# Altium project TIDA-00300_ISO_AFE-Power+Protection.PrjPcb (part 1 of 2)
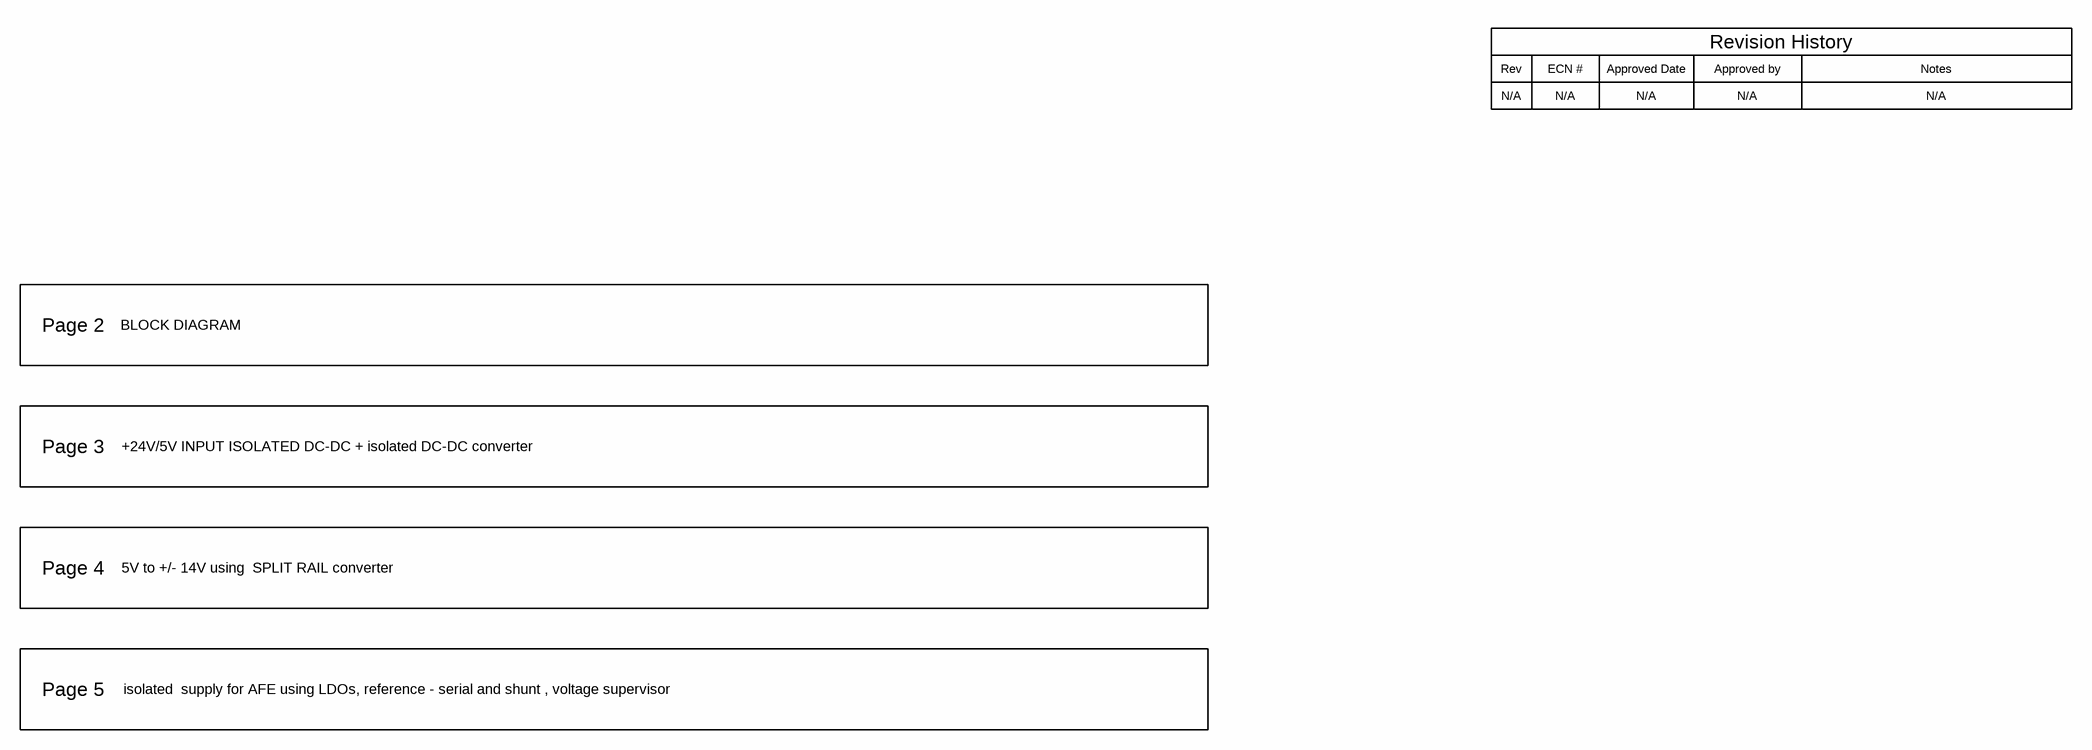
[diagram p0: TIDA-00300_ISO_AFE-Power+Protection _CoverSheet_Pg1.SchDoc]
CopyrightYear: 2019; PCB_Layout: Avinash N; PCB_Rev: E1; PRJ_Customer: Public Release; PRJ_Engineer: Sreenivasa; PRJ_Number: TIDA-00300_ISO_AFE-Power+Protection; PRJ_Title: TIDA-00300_ISO_AFE-Power+Protection; SCH_Rev: E1; TechSupport: http://www.ti.com/support; TID: 00300
6 sheets, 241 parts. Net scope: global (net labels, ports and power ports of the same name join across sheets).
Board file: TIDA-00300_ISO_AFE-Power+Protection.PcbDoc
Sheets:
  TIDA-00300_ISO_AFE-Power+Protection _CoverSheet_Pg1.SchDoc
  TIDA-00300_ISO_AFE-Power+Protection _ Block Diagram_Pg2.SchDoc
  TIDA-00300_ISO_AFE-Power+Protection _Pg3.SchDoc
  TIDA-00300_ISO_AFE-Power+Protection _Pg4.SchDoc
  TIDA-00300_ISO_AFE-Power+Protection _Pg5.SchDoc
  TIDA-00300_ISO_AFE-Power+Protection _EVM_Hardware_Pg6.SchDoc

## Sheet TIDA-00300_ISO_AFE-Power+Protection _CoverSheet_Pg1.SchDoc: Coversheet
size 431 x 279 mm; Date: Not shown in title block; ApprovedBy: Not shown in title block; CheckedBy: Not shown in title block; Author: Not shown in title block; CompanyName: Not shown in title block; DrawnBy: Sreenivasa; Engineer: Not shown in title block; Organization: Not shown in title block; Address1: Not shown in title block; Address2: Not shown in title block; Address3: Not shown in title block; Address4: Not shown in title block; DocumentNumber: 1; Revision: Use project parameter SCH_Rev; SheetNumber: 1; SheetTotal: 6; PageSetup: Record=PageOptions¦CenterHorizontal=True¦CenterVertical=True¦PrintScale=1.00¦XCorrection=1.00¦YCorrection=1.00¦PrintKind=0¦BorderSize=5000000¦LeftOffset=0¦BottomOffset=0¦Orientation=2¦PaperLength=1000¦PaperWidth=1000¦Scale=100¦PaperSource=15¦PrintQuality=600¦MediaType=1¦DitherType=10¦PaperKind=Letter¦PrintScaleMode=1

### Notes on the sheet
- Rev
- N/A
- ECN #
- Approved Date
- Approved by
- Revision History
- Notes
- Page 2
- BLOCK DIAGRAM
- Page 3
- +24V/5V INPUT ISOLATED DC-DC + isolated DC-DC converter
- Page 4
- 5V to +/- 14V using  SPLIT RAIL converter
- Page 5
- isolated  supply for AFE using LDOs, reference - serial and shunt , voltage supervisor

## Sheet TIDA-00300_ISO_AFE-Power+Protection _ Block Diagram_Pg2.SchDoc: Block Diagram
size 431 x 279 mm; Date: Not shown in title block; ApprovedBy: Not shown in title block; CheckedBy: Not shown in title block; Author: Not shown in title block; CompanyName: Not shown in title block; DrawnBy: Sreenivasa; Engineer: Sreenivasa; Organization: Not shown in title block; Address1: Not shown in title block; Address2: Not shown in title block; Address3: Not shown in title block; Address4: Not shown in title block; DocumentNumber: 1; Revision: Use project parameter SCH_Rev; SheetNumber: 2; SheetTotal: 6; PageSetup: Record=PageOptions¦CenterHorizontal=True¦CenterVertical=True¦PrintScale=1.00¦XCorrection=1.00¦YCorrection=1.00¦PrintKind=0¦BorderSize=5000000¦LeftOffset=0¦BottomOffset=0¦Orientation=2¦PaperLength=1000¦PaperWidth=1000¦Scale=100¦PaperSource=15¦PrintQuality=600¦MediaType=1¦DitherType=10¦PaperKind=Letter¦PrintScaleMode=1
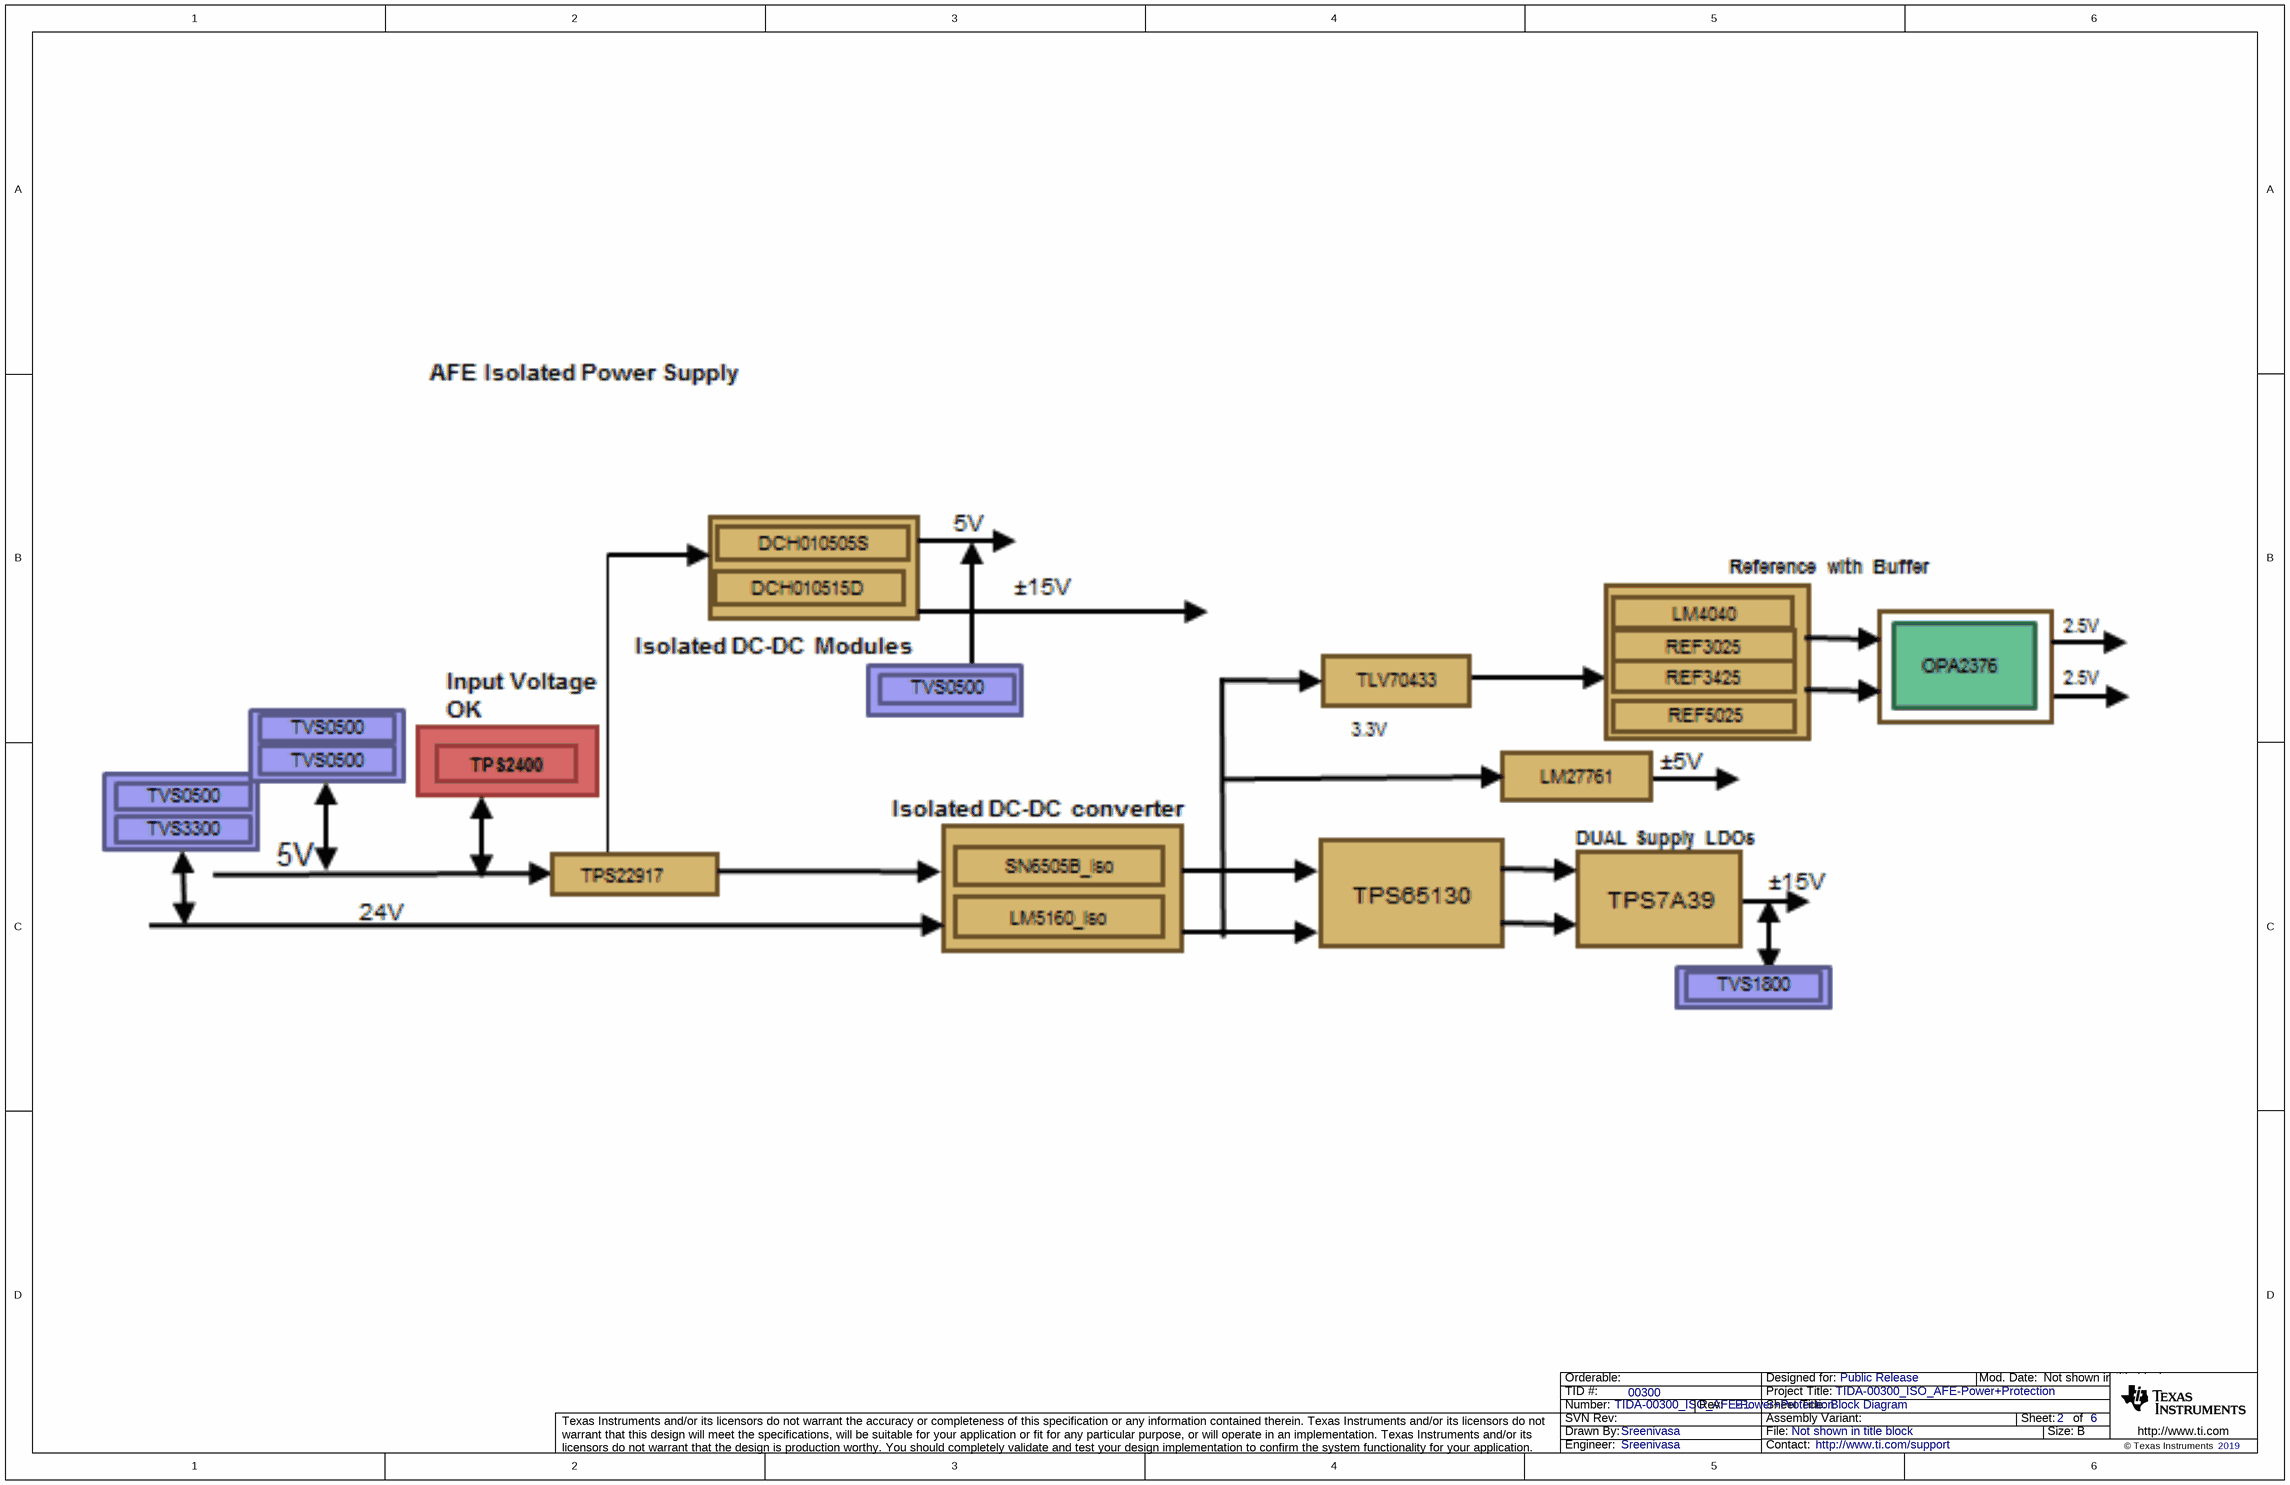
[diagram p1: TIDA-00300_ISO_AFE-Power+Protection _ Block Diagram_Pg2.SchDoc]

## Sheet TIDA-00300_ISO_AFE-Power+Protection _Pg3.SchDoc: +24V/5V INPUT ISOLATED DC-DC
size 431 x 279 mm; Date: Not shown in title block; ApprovedBy: Not shown in title block; CheckedBy: Not shown in title block; Author: Not shown in title block; CompanyName: Not shown in title block; DrawnBy: Sreenivasa; Engineer: Not shown in title block; Organization: Not shown in title block; Address1: Not shown in title block; Address2: Not shown in title block; Address3: Not shown in title block; Address4: Not shown in title block; DocumentNumber: 1; Revision: Use project parameter SCH_Rev; SheetNumber: 3; SheetTotal: 6; PageSetup: Record=PageOptions¦CenterHorizontal=True¦CenterVertical=True¦PrintScale=0.62¦XCorrection=1.00¦YCorrection=1.00¦PrintKind=0¦BorderSize=5000000¦LeftOffset=0¦BottomOffset=0¦Orientation=2¦PaperLength=1000¦PaperWidth=1000¦Scale=100¦PaperSource=15¦PrintQuality=600¦MediaType=1¦DitherType=10¦PrintScaleMode=1¦PaperKind=Letter
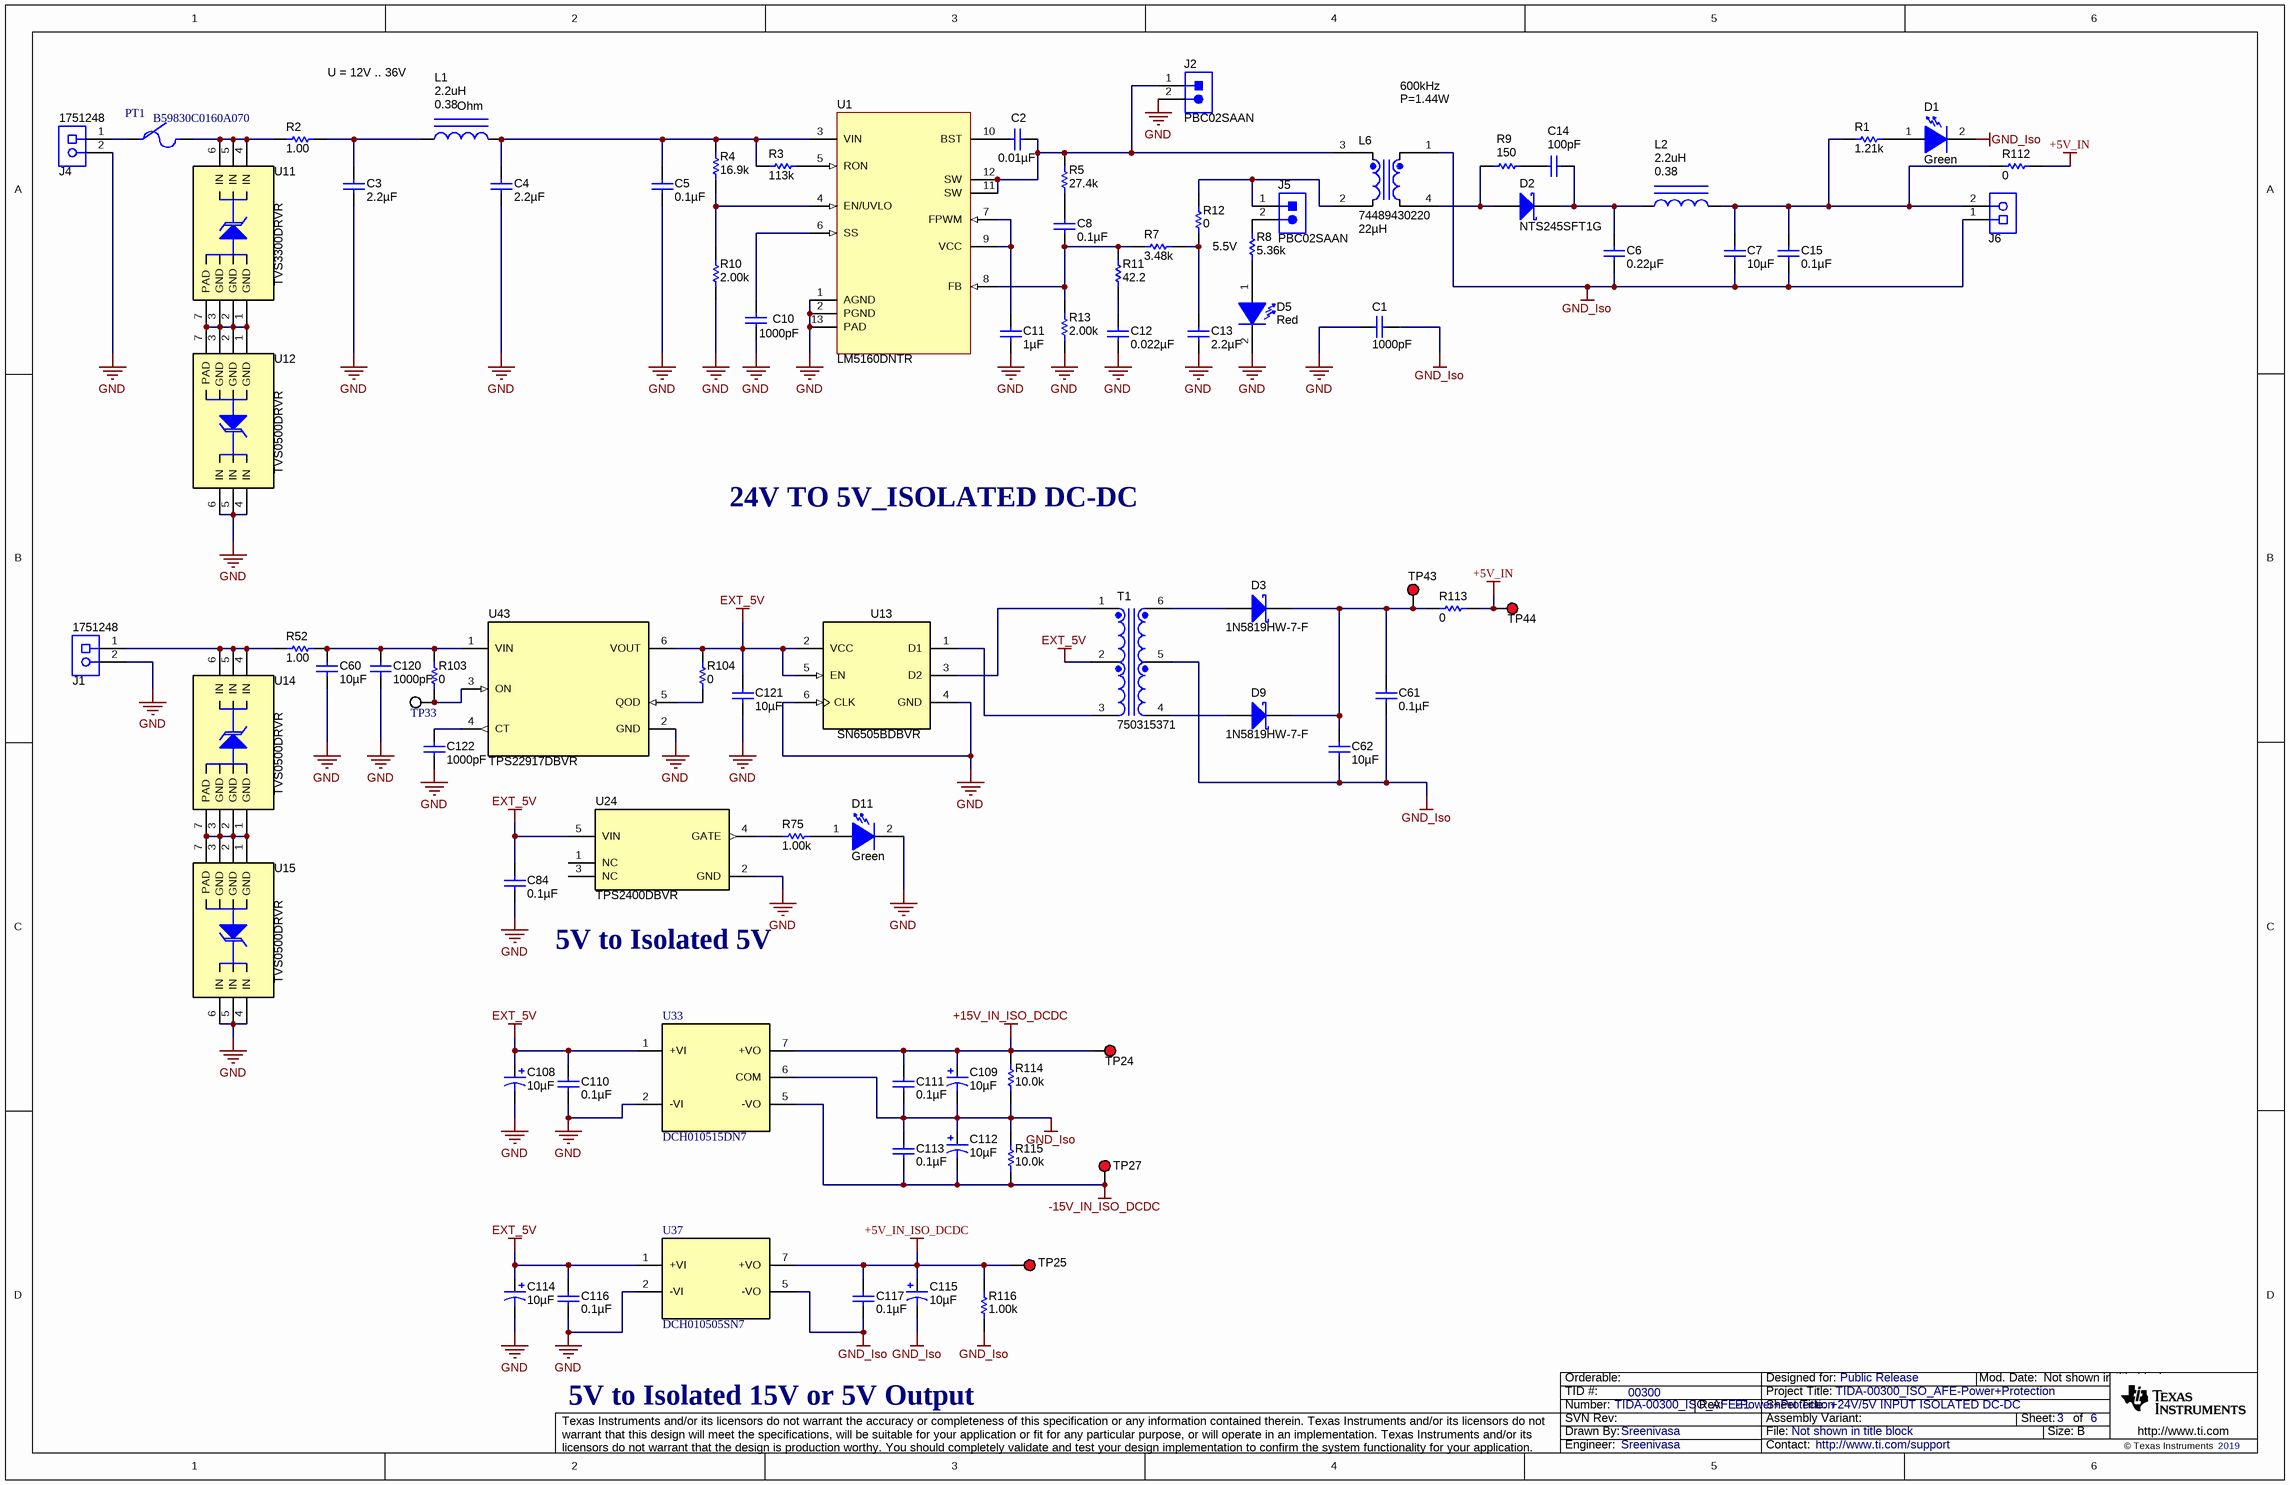
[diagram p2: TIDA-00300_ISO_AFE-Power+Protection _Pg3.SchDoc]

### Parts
C1  ValueDisplayed: 1000pF  [1206_190]  (hidden comment: 1206GC102KAZ1A)
C2  ValueDisplayed: 0.01µF  [0603S]  (hidden comment: CGA3E2X7R1H103K080AA)
C3  ValueDisplayed: 2.2µF  [1206]  (hidden comment: UMK316B7225KL-T)
C4  ValueDisplayed: 2.2µF  [1206]  (hidden comment: UMK316B7225KL-T)
C5  ValueDisplayed: 0.1µF  [0603S]  (hidden comment: C0603X124K5RAC7867)
C6  ValueDisplayed: 0.22µF  [0603]  (hidden comment: 885012206048)
C7  ValueDisplayed: 10µF  [0805_HV]  (hidden comment: GRM21BC71E106KE11L)
C8  ValueDisplayed: 0.1µF  [0603S]  (hidden comment: C0603X124K5RAC7867)
C10  ValueDisplayed: 1000pF  [0603S]  (hidden comment: 885012206034)
C11  ValueDisplayed: 1µF  [0603S]  (hidden comment: CGA3E1X7R1E105K080AC)
C12  ValueDisplayed: 0.022µF  [0603S]  (hidden comment: C1608X7R1H223K080AA)
C13  ValueDisplayed: 2.2µF  [0603]  (hidden comment: C1608X7R1A225K080AC)
C14  ValueDisplayed: 100pF  [0603S]  (hidden comment: GCM1885C1H101JA16D)
C15  ValueDisplayed: 0.1µF  [0603S]  (hidden comment: C0603X124K5RAC7867)
C60  ValueDisplayed: 10µF  [0805_HV]  (hidden comment: C2012X5R1E106K085AC)
C61  ValueDisplayed: 0.1µF  [0603]  (hidden comment: 06033D104KAT2A)
C62  ValueDisplayed: 10µF  [0805_HV]  (hidden comment: C2012X5R1E106K085AC)
C84  ValueDisplayed: 0.1µF  [0603S]  (hidden comment: C0603X124K5RAC7867)
C108  ValueDisplayed: 10µF  [6032-28]  (hidden comment: 593D106X9025C2TE3)
C109  ValueDisplayed: 10µF  [6032-28]  (hidden comment: 593D106X9025C2TE3)
C110  ValueDisplayed: 0.1µF  [0603]  (hidden comment: 06033D104KAT2A)
C111  ValueDisplayed: 0.1µF  [0603]  (hidden comment: 06033D104KAT2A)
C112  ValueDisplayed: 10µF  [6032-28]  (hidden comment: 593D106X9025C2TE3)
C113  ValueDisplayed: 0.1µF  [0603]  (hidden comment: 06033D104KAT2A)
C114  ValueDisplayed: 10µF  [6032-28]  (hidden comment: 593D106X9025C2TE3)
C115  ValueDisplayed: 10µF  [6032-28]  (hidden comment: 593D106X9025C2TE3)
C116  ValueDisplayed: 0.1µF  [0603]  (hidden comment: 06033D104KAT2A)
C117  ValueDisplayed: 0.1µF  [0603]  (hidden comment: 06033D104KAT2A)
C120  ValueDisplayed: 1000pF  [0402]  (hidden comment: CGA2B2C0G1H102J050BA)
C121  ValueDisplayed: 10µF  [0805_HV]  (hidden comment: C2012X5R1E106K085AC)
C122  ValueDisplayed: 1000pF  [0402]  (hidden comment: CGA2B2C0G1H102J050BA)
D1  value Green  [LED_LTST-C190_G]  (hidden comment: LTST-C190KGKT)
D2  NTS245SFT1G  [SOD-123FL]
D3  1N5819HW-7-F  [SOD-123]
D5  value Red  [LED_LTST-C190_Red]  (hidden comment: LTST-C190CKT)
D9  1N5819HW-7-F  [SOD-123]
D11  value Green  [LED_LTST-C190_G]  (hidden comment: LTST-C190KGKT)
J1  1751248  [CONN_1751248]
J2  PBC02SAAN  [Sullins_PBC02SAAN]
J4  1751248  [CONN_1751248]
J5  PBC02SAAN  [Sullins_PBC02SAAN]
J6  1751248  [CONN_1751248]  (value not drawn)
L1  2.2uH  DCR_ohm: 0.38  [0603L]
L2  2.2uH  DCR_ohm: 0.38  [0603]
L6  74489430220  ValueDisplayed: 22µH  [WE-TDC_8018]
PT1  B59830C0160A070  [POLYSWITCH_RXE135]
R1  ValueDisplayed: 1.21k  [0603S]  (hidden comment: CRCW06031K21FKEA)
R2  ValueDisplayed: 1.00  [0603S]  (hidden comment: CRCW06031R00FKEA)
R3  ValueDisplayed: 113k  [0603S]  (hidden comment: CRCW0603113KFKEA)
R4  ValueDisplayed: 16.9k  [0603S]  (hidden comment: CRCW060316K9FKEA)
R5  ValueDisplayed: 27.4k  [0603S]  (hidden comment: CRCW060327K4FKEA)
R7  ValueDisplayed: 3.48k  [0603S]  (hidden comment: CRCW06033K48FKEA)
R8  ValueDisplayed: 5.36k  [0603S]  (hidden comment: CRCW06035K36FKEA)
R9  ValueDisplayed: 150  [0603S]  (hidden comment: CRCW0603150RFKEA)
R10  ValueDisplayed: 2.00k  [0603S]  (hidden comment: CRCW06032K00FKEA)
R11  ValueDisplayed: 42.2  [0603S]  (hidden comment: CRCW060342R2FKEA)
R12  ValueDisplayed: 0  [0603S]  (hidden comment: ERJ-3GEY0R00V)
R13  ValueDisplayed: 2.00k  [0603S]  (hidden comment: CRCW06032K00FKEA)
R52  ValueDisplayed: 1.00  [0603S]  (hidden comment: CRCW06031R00FKEA)
R75  ValueDisplayed: 1.00k  [0603]  (hidden comment: ERJ-3EKF1001V)
R103  ValueDisplayed: 0  [0603]  (hidden comment: ERJ-3GEY0R00V)
R104  ValueDisplayed: 0  [0603]  (hidden comment: ERJ-3GEY0R00V)
R112  ValueDisplayed: 0  [0805_HV]  (hidden comment: ERJ-6GEY0R00V)
R113  ValueDisplayed: 0  [0805_HV]  (hidden comment: ERJ-6GEY0R00V)
R114  ValueDisplayed: 10.0k  [0603]  (hidden comment: RC0603FR-0710KL)
R115  ValueDisplayed: 10.0k  [0603]  (hidden comment: RC0603FR-0710KL)
R116  ValueDisplayed: 1.00k  [0603]  (hidden comment: CRCW06031K00FKEA)
T1  750315371  [Wurth_750315371]
TP24  5000  [Keystone5000]  (value not drawn)
TP25  5000  [Keystone5000]  (value not drawn)
TP27  5000  [Keystone5000]  (value not drawn)
TP33  5002  [Keystone5002]  (value not drawn)
TP43  5000  [Keystone5000]  (value not drawn)
TP44  5000  [Keystone5000]  (value not drawn)
U1  LM5160DNTR  [DNT0012B]
U11  TVS3300DRVR  [DRV0006A]
U12  TVS0500DRVR  [DRV0006A]
U13  SN6505BDBVR  [DBV0006A_N]
U14  TVS0500DRVR  [DRV0006A]
U15  TVS0500DRVR  [DRV0006A]
U24  TPS2400DBVR  [DBV0005A_N]
U33  DCH010515DN7  [EDJ0005A]
U37  DCH010505SN7  [EDJ0004A]
U43  TPS22917DBVR  [DBV0006A_N]

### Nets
+5V_IN: R112.2 R113.2 TP44.1
+5V_IN_ISO_DCDC: C115.1(+) C117.1 R116.2 TP25.1 U37.7(+VO)
+15V_IN_ISO_DCDC: C109.1(+) C111.1 R114.1 TP24.1 U33.7(+VO)
-15V_IN_ISO_DCDC: C112.2(-) C113.2 R115.2 TP27.1 U33.5(-VO)
EXT_5V: C84.1 C108.1(+) C110.1 C114.1(+) C116.1 C121.1 R104.2 T1.2 U13.2(VCC) U13.5(EN) U24.5(VIN) U33.1(+VI) U37.1(+VI) U43.6(VOUT)
GND: C1.2 C3.2 C4.2 C5.2 C10.2 C11.2 C12.2 C13.2 C60.2 C84.2 C108.2(-) C110.2 C114.2(-) C116.2 C120.2 C121.2 C122.2 D5.2(K) D11.2(K) J1.2 J2.2 J4.2 R10.1 R13.1 U1.1(AGND) U1.2(PGND) U1.13(PAD) U12.4(IN) U12.5(IN) U12.6(IN) U13.4(GND) U13.6(CLK) U15.4(IN) U15.5(IN) U15.6(IN) U24.2(GND) U33.2(-VI) U37.2(-VI) U43.2(GND)
GND_Iso: C1.1 C6.2 C7.2 C15.2 C61.2 C62.1 C109.2(-) C111.2 C112.1(+) C113.1 C115.2(-) C117.2 D1.2(K) J6.1 L6.1 R114.2 R115.1 R116.1 T1.5 U33.6(COM) U37.5(-VO)
NetC2_1: C2.1 U1.10(BST)
NetC2_2: C2.2 J2.1 L6.3 R5.1 U1.11(SW) U1.12(SW)
NetC3_1: C3.1 L1.1 R2.1
NetC4_1: C4.1 C5.1 L1.2 R3.1 R4.2 U1.3(VIN)
NetC6_1: C6.1 C14.2 D2.1(K) L2.1
NetC7_1: C7.1 C15.1 J6.2 L2.2 R1.1 R112.1
NetC8_1: C8.1 R5.2
NetC8_2: C8.2 R7.1 R11.2 R13.2 U1.8(FB)
NetC10_1: C10.1 U1.6(SS)
NetC11_1: C11.1 U1.7(FPWM) U1.9(VCC)
NetC12_1: C12.1 R11.1
NetC13_1: C13.1 R7.2 R12.1
NetC14_1: C14.1 R9.1
NetC60_1: C60.1 C120.1 R52.1 R103.2 U43.1(VIN)
NetC61_1: C61.1 C62.2 D3.1(K) D9.1(K) R113.1 TP43.1
NetC122_1: C122.1 U43.4(CT)
NetD1_1: D1.1(A) R1.2
NetD2_2: D2.2(A) L6.4 R9.2
NetD3_2: D3.2(A) T1.6
NetD5_1: D5.1(A) R8.1
NetD9_2: D9.2(A) T1.4
NetD11_1: D11.1(A) R75.2
NetJ1_1: J1.1 R52.2 U14.4(IN) U14.5(IN) U14.6(IN)
NetJ4_1: J4.1 PT1.1
NetJ5_1: J5.1 L6.2 R12.2
NetJ5_2: J5.2 R8.2
NetPT1_2: PT1.2 R2.2 U11.4(IN) U11.5(IN) U11.6(IN)
NetR3_2: R3.2 U1.5(RON)
NetR4_1: R4.1 R10.2 U1.4(EN/UVLO)
NetR75_1: R75.1 U24.4(GATE)
NetR103_1: R103.1 TP33.1 U43.3(ON)
NetR104_1: R104.1 U43.5(QOD)
NetT1_1: T1.1 U13.3(D2)
NetT1_3: T1.3 U13.1(D1)
NetU11_1: U11.1(GND) U11.2(GND) U11.3(GND) U11.7(PAD) U12.1(GND) U12.2(GND) U12.3(GND) U12.7(PAD)
NetU14_1: U14.1(GND) U14.2(GND) U14.3(GND) U14.7(PAD) U15.1(GND) U15.2(GND) U15.3(GND) U15.7(PAD)

Not connected (* = marked no-connect by the designer): U24 1(NC) 3(NC)

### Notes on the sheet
- U = 12V .. 36V
- (near L6) P=1.44W
- 600kHz
- (near L1) Ohm
- 5.5V
- 24V TO 5V_ISOLATED DC-DC
- 5V to Isolated 5V
- 5V to Isolated 15V or 5V Output

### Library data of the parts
C1 = 202R18W102KV4E: CAP, CERM, 1000 pF, 2000 V, +/- 10%, X7R, 1206_190; Manufacturer: AVX; Polarized: N; CompType: Capacitor; Value: 1000pF; U/M: EA; Cap_F: 0.000000001; Tolerance_%: 10; Value1: Unknown; VDC_V: 2000; Value2: 2000V; TaMin_C: -55; TaMax_C: 125; Cap_Case: 1206
C2 = C0603C103J5RACTU: CAP, CERM, 0.01 µF, 50 V, +/- 5%, X7R, 0603; Manufacturer: TDK Corporation; Polarized: N; CompType: Capacitor; Value: 0.01uF; U/M: EA; Cap_F: 0.00000001; Tolerance_%: 5; Value1: Unknown; VDC_V: 50; Value2: 50V; TaMin_C: -55; TaMax_C: 125; Cap_Case: 0603; AEC Category: Q200
C3 C4 = UMK316B7225KL-T: CAP, CERM, 2.2 µF, 50 V,+/- 10%, X7R, 1206; Manufacturer: Taiyo Yuden; Polarized: N; CompType: Capacitor; Value: 2.2uF; U/M: EA; Cap_F: 0.0000022; Tolerance_%: 10; VDC_V: 50; Value2: 50V; TaMin_C: -55; TaMax_C: 125; AEC Category: Q200; SizeArea_mm2: 5.12; SizeAreaWB_mm2: 10.92; SizeX_mm: 3.2; SizeY_mm: 1.6; SizeZ_mm: 1.35
C5 C8 C15 C84 = C1608X7R1H104K: CAP, CERM, 0.12µF ±10% 50V Ceramic Capacitor X7R 0603; Manufacturer: KEMET; Polarized: N; Value: 0.1uF; U/M: EA; Cap_F: 0.0000001; Tolerance_%: 10; ESR_ohm: 0.017; Value1: 0.017 ohm; VDC_V: 50; TaMin_C: -55; TaMax_C: 125; Cap_Case: 0603; AEC Category: Q200
C6 = 885012206048: CAP, CERM, 0.22 µF, 16 V, +/- 10%, X7R, 0603; Manufacturer: Wurth Elektronik; Polarized: N; CompType: Capacitor; Value: 0.22uF; U/M: EA; Cap_F: 0.00000022; Tolerance_%: 10; Value1: Unknown; VDC_V: 16; Value2: 16V; TaMin_C: -55; TaMax_C: 125; AEC Category: Q200
C7 = GRM21BC71E106KE11L: CAP, CERM, 10 µF, 25 V,+/- 10%, X7S, 0805; Manufacturer: MuRata; Polarized: N; CompType: Capacitor; Value: 10uF; U/M: EA; Cap_F: 0.00001; Tolerance_%: 10; VDC_V: 25; Value2: 25V; TaMin_C: -55; TaMax_C: 125; Cap_Case: 0805; AEC Category: Q200; SizeArea_mm2: 2.5; SizeAreaWB_mm2: 6.75; SizeX_mm: 2; SizeY_mm: 1.25; SizeZ_mm: 1.45
C10 = 885012206034: CAP, CERM, 1000 pF, 16 V, +/- 10%, X7R, 0603; Manufacturer: Wurth Elektronik; Polarized: N; CompType: Capacitor; Value: 1000pF; U/M: EA; Cap_F: 0.000000001; Tolerance_%: 10; Value1: Unknown; VDC_V: 16; Value2: 16V; TaMin_C: -55; TaMax_C: 125; Cap_Case: 0603; AEC Category: Q200
C11 = GRM188R71E105KA12D: CAP, CERM, 1 µF, 25 V, +/- 10%, X7R, 0603; Manufacturer: TDK Corporation; Polarized: N; CompType: Capacitor; Value: 1uF; U/M: EA; Cap_F: 0.000001; Tolerance_%: 10; Value1: Unknown; VDC_V: 25; Value2: 25V; TaMin_C: -55; TaMax_C: 125; Cap_Case: 0603; AEC Category: Q200
C12 = GRM188R71H223KA01D: CAP, CERM, 0.022 µF, 50 V, +/- 10%, X7R, 0603; Manufacturer: TDK Corporation; Polarized: N; CompType: Capacitor; Value: 0.022uF; U/M: EA; Cap_F: 0.000000022; Tolerance_%: 10; Value1: Unknown; VDC_V: 50; Value2: 50V; TaMin_C: -55; TaMax_C: 125; Cap_Case: 0603; AEC Category: Q200
C13 = C1608X7R1A225K080AC: CAP, CERM, 2.2 µF, 10 V,+/- 10%, X7R, 0603; Manufacturer: TDK; Polarized: N; CompType: Capacitor; Value: 2.2uF; U/M: EA; Cap_F: 0.0000022; Tolerance_%: 10; ESR_ohm: 0.004058; Value1: 0.004058 ohm; Value2: 10V; IRMS_A: 2.58266; TaMin_C: -55; TaMax_C: 125; AEC Category: Q200; SizeArea_mm2: 1.28; SizeAreaWB_mm2: 4.68; SizeX_mm: 1.6; SizeY_mm: 0.8; SizeZ_mm: 1; Green_Lifecycle: Active; Green_REACh: Passed
C14 = C0603C101J5GACTU: CAP, CERM, 100 pF, 50 V, +/- 5%, C0G/NP0, 0603; Manufacturer: Murata; Polarized: N; CompType: Capacitor; Value: 100pF; U/M: EA; Cap_F: 0.0000000001; Tolerance_%: 5; Value1: Unknown; VDC_V: 50; Value2: 50V; TaMin_C: -55; TaMax_C: 125; Cap_Case: 0603; AEC Category: Q200
C60 C62 C121 = GRM21BR61E106KA73L: CAP, CERM, 10 µF, 25 V, +/- 10%, X5R, 0805; Manufacturer: TDK Corporation; Polarized: N; CompType: Capacitor; Value: 10uF; U/M: EA; Cap_F: 0.00001; Tolerance_%: 10; Value1: Unknown; VDC_V: 25; Value2: 25V; TaMin_C: -55; TaMax_C: 85; Cap_Case: 0805; AEC Category: Q200
C61 = 06033D104KAT2A: CAP, CERM, 0.1 µF, 25 V,+/- 10%, X5R, 0603; Manufacturer: AVX; Polarized: N; CompType: Capacitor; Value: 0.1uF; U/M: EA; Cap_F: 0.0000001; Tolerance_%: 10; ESR_ohm: 0.048; Value1: 0.048 ohm; VDC_V: 25; Value2: 25V; IRMS_A: 0.53; TaMin_C: -55; TaMax_C: 85; AEC Category: Q200; SizeArea_mm2: 1.28; SizeAreaWB_mm2: 4.68; SizeX_mm: 1.6; SizeY_mm: 0.8; SizeZ_mm: 1; Green_Lifecycle: Active; Green_REACh: Passed
C108 C109 C112 C114 C115 = 593D106X9025C2TE3: CAP, TA, 10 µF, 25 V, +/- 10%, 0.45 ohm, SMD; Manufacturer: Vishay-Sprague; Polarized: Y; CompType: Capacitor; Value: 10uF; U/M: EA; Cap_F: 0.00001; Tolerance_%: 10; VDC_V: 25; Value2: 25V; ESR_ohm: 0.45; IRMS_A: 0.49; TaMin_C: -55; TaMax_C: 125; Cap_Case: C; SizeAreaWB_mm2: 41.6; SizeArea_mm2: 19.2; SizeX_mm: 6; SizeY_mm: 3.2; SizeZ_mm: 2.8; AEC Category: Q200
C110 C111 C113 C116 C117 = 06033D104KAT2A: CAP, CERM, 0.1 µF, 25 V,+/- 10%, X5R, 0603; Manufacturer: AVX; Polarized: N; CompType: Capacitor; Value: 0.1uF; U/M: EA; Cap_F: 0.0000001; Tolerance_%: 10; ESR_ohm: 0.048; Value1: 0.048 ohm; VDC_V: 25; Value2: 25V; IRMS_A: 0.53; TaMin_C: -55; TaMax_C: 85; SizeArea_mm2: 1.28; SizeAreaWB_mm2: 4.68; SizeX_mm: 1.6; SizeY_mm: 0.8; SizeZ_mm: 1; AEC Category: Q200; Green_Lifecycle: Active; Green_REACh: Passed
C120 C122 = CGA2B2C0G1H102J050BA: CAP, CERM, 1000 pF, 50 V,+/- 5%, C0G/NP0, AEC-Q200 Grade 1, 0402; Manufacturer: TDK; Polarized: N; CompType: Capacitor; Value: 1000pF; U/M: EA; Cap_F: 0.000000001; Tolerance_%: 5; VDC_V: 50; Value2: 50V; TaMin_C: -55; TaMax_C: 125; SizeArea_mm2: 0.5; SizeAreaWB_mm2: 3; SizeX_mm: 1; SizeZ_mm: 0.6; AEC Category: Q200; AEC Qualified: Y; Green_Lifecycle: Active; Green_REACh: Passed
D1 D11 = LTST-C190KGKT: LED, Green, SMD; Manufacturer: Lite-On; Type: AlInGaP; Vf_V: 2; Value2: 2V; Io_A: 0.03; Tjmax_C: 85; Value1: W; U/M: EA
D2 = NTS245SFT1G: Diode, Schottky, 45 V, 2 A, AEC-Q101, SOD-123FL; Manufacturer: ON Semiconductor; U/M: EA; Vf_V: 0.63; Value: 45V; Value1: 2A; Value2: 0.63V; Io_A: 2; Vr_V: 45; TJmax_C: 150; AEC Category: Q101; AEC Qualified: Y
D3 D9 = 1N5819HW-7-F: Diode, Schottky, 40 V, 1 A, SOD-123; Manufacturer: Diodes Inc.; U/M: EA; Vf_V: 0.45; Value: 40V; Value1: 1A; Value2: 0.45V; Io_A: 1; Vr_V: 40; TJmax_C: 125; SizeAreaWB_mm2: 13.095; SizeArea_mm2: 6.545; SizeX_mm: 3.85; SizeY_mm: 1.7; SizeZ_mm: 1.35; AEC Category: Q101
D5 = LTST-C190CKT: LED, Red, SMD; Manufacturer: Lite-On; Vf_V: 2; Value2: 2V; Io_A: 0.02; Tjmax_C: 85; Power_TotalModule: 0.0625; Value1: 0.0625W; U/M: EA
J1 J4 J6 = 1751248: Conn Term Block, 2POS, 3.5mm, TH; Manufacturer: Phoenix Contact; CompType: Terminal Block; SymbolCreator: a0412235
J2 J5 = PBC02SAAN: Header, 100mil, 2x1, Gold, TH; Manufacturer: Sullins Connector Solutions; SymbolCreator: a0412235; Pitch_mm: 2.54; Gender: Male; Shrouded: N; Row_Count: 1; Current_A: 3; Voltage_V: 1800; Cert_UL: Y; Green_Lifecycle: Active; Green_REACh: Passed
L1 L2 = LQM18PN2R2MFH: Inductor, Ferrite, 2.2 µH, 0.35 A, 0.38 ohm, SMD; Manufacturer: MuRata; Imax_A: 0.35; Value2: 0.35A; Ind_H: 2.2E-6; ValueDisplayed: 2.2µH; Irms: 0.9A @ 40C rise; Isat: 0.35A @ 30% inductance drop; AEC Category: Q200
L6 = 74489430220: Coupled inductor, 22 µH, 1.1 A, 0.48 ohm, SMD; Manufacturer: Wurth Elektronik; SymbolCreator: Altium; Value: 22uH; Ind_H: 22.0E-6; DCR_ohm: 0.48
PT1 = POLYSWITCH_RXE135: PTC THERMISTOR C 830-A 160-A 70; Manufacturer: Raychem; Manufacturer: EPCOS (TDK); Area: 93750
R1 = CRCW06031K21FKEA: RES, 1.21 k, 1%, 0.1 W, 0603; Manufacturer: Vishay-Dale; CompType: Resistor; Value: 1.21k; Res_ohm: 1210; Value_Code: 1k21; Tolerance_%: 1; Power_W: 0.1; Value2: 0.1W; VDC_V: 75; TempCo: 100 ppm/C; EIA_Code: E96; U/M: EA; AEC Category: Q200
R2 R52 = CRCW06031R00FKEA: RES, 1.00, 1%, 0.1 W, 0603; Manufacturer: Vishay-Dale; CompType: Resistor; Value: 1.00; Res_ohm: 1; Value_Code: 1R00; Power_W: 0.1; Value2: 0.1W; VDC_V: 75; TempCo: 100 ppm/C; EIA_Code: E96; U/M: EA; AEC Category: Q200
R3 = CRCW0603113KFKEA: RES, 113 k, 1%, 0.1 W, 0603; Manufacturer: Vishay-Dale; CompType: Resistor; Value: 113k; Res_ohm: 113000; Tolerance_%: 1; Power_W: 0.1; Value2: 0.1W; VDC_V: 75; TempCo: 100 ppm/C; EIA_Code: E96; U/M: EA; AEC Category: Q200
R4 = CRCW060316K9FKEA: RES, 16.9 k, 1%, 0.1 W, 0603; Manufacturer: Vishay-Dale; CompType: Resistor; Value: 16.9k; Res_ohm: 16900; Value_Code: 16k9; Tolerance_%: 1; Power_W: 0.1; Value2: 0.1W; VDC_V: 75; TempCo: 100 ppm/C; EIA_Code: E96; U/M: EA; AEC Category: Q200
R5 = CRCW060327K4FKEA: RES, 27.4 k, 1%, 0.1 W, 0603; Manufacturer: Vishay-Dale; CompType: Resistor; Value: 27.4k; Res_ohm: 27400; Value_Code: 27k4; Tolerance_%: 1; Power_W: 0.1; Value2: 0.1W; VDC_V: 75; TempCo: 100 ppm/C; EIA_Code: E96; U/M: EA; AEC Category: Q200
R7 = CRCW06033K48FKEA: RES, 3.48 k, 1%, 0.1 W, 0603; Manufacturer: Vishay-Dale; CompType: Resistor; Value: 3.48k; Res_ohm: 3480; Value_Code: 3k48; Tolerance_%: 1; Power_W: 0.1; Value2: 0.1W; VDC_V: 75; TempCo: 100 ppm/C; EIA_Code: E96; U/M: EA; AEC Category: Q200
R8 = CRCW06035K36FKEA: RES, 5.36 k, 1%, 0.1 W, 0603; Manufacturer: Vishay-Dale; CompType: Resistor; Value: 5.36k; Res_ohm: 5360; Value_Code: 5k36; Tolerance_%: 1; Power_W: 0.1; Value2: 0.1W; VDC_V: 75; TempCo: 100 ppm/C; EIA_Code: E96; U/M: EA; AEC Category: Q200
R9 = CRCW0603150RFKEA: RES, 150, 1%, 0.1 W, 0603; Manufacturer: Vishay-Dale; CompType: Resistor; Value: 150; Value_Code: 150R; Tolerance_%: 1; Power_W: 0.1; Value2: 0.1W; VDC_V: 75; TempCo: 100 ppm/C; EIA_Code: E96; U/M: EA; AEC Category: Q200
R10 R13 = CRCW06032K00FKEA: RES, 2.00 k, 1%, 0.1 W, 0603; Manufacturer: Vishay-Dale; CompType: Resistor; Value: 2.00k; Res_ohm: 2000; Value_Code: 2k00; Tolerance_%: 1; Power_W: 0.1; Value2: 0.1W; VDC_V: 75; TempCo: 100 ppm/C; EIA_Code: E96; U/M: EA; AEC Category: Q200
R11 = CRCW060342R2FKEA: RES, 42.2, 1%, 0.1 W, 0603; Manufacturer: Vishay-Dale; CompType: Resistor; Value: 42.2; Value_Code: 42R2; Tolerance_%: 1; Power_W: 0.1; Value2: 0.1W; VDC_V: 75; TempCo: 100 ppm/C; EIA_Code: E96; U/M: EA; AEC Category: Q200
R12 = ERJ-3GEY0R00V: RES, 0, 5%, 0.1 W, 0603; Manufacturer: Panasonic; CompType: Resistor; Value: 0; Value_Code: 0000; Tolerance_%: 5; Power_W: 0.1; Value2: 0.1W; VDC_V: 50; TempCo: 600 ppm/C; EIA_Code: E24; U/M: EA; AEC Category: Q200
R75 = ERJ-3EKF1001V: RES, 1.00 k, 1%, 0.1 W, AEC-Q200 Grade 0, 0603; Manufacturer: Panasonic; CompType: Resistor; Value: 1.00k; Res_ohm: 1000; Value_Code: 1k00; Tolerance_%: 1; Power_W: 0.1; Value2: 0.1W; VDC_V: 75; TempCo: 100 ppm/C; SizeArea_mm2: 1.28; SizeX_mm: 1.6; SizeY_mm: 0.8; EIA_Code: E96; U/M: EA; AEC Category: Q200; AEC Qualified: Y; AEC Grade: 0; Green_Lifecycle: Active; Green_REACh: Passed
R103 R104 = ERJ-3GEY0R00V: RES, 0, 5%, 0.1 W, 0603; Manufacturer: Panasonic; CompType: Resistor; Value: 0; Value_Code: 0000; Tolerance_%: 5; Power_W: 0.1; Value2: 0.1W; VDC_V: 50; TempCo: 600 ppm/C; SizeArea_mm2: 1.28; SizeX_mm: 1.6; SizeY_mm: 0.8; SizeZ_mm: 1; EIA_Code: E24; U/M: EA; AEC Category: Q200; Green_Lifecycle: Active; Green_REACh: Passed
R112 R113 = ERJ-6GEY0R00V: RES, 0, 5%, 0.125 W, 0805; Manufacturer: Panasonic; CompType: Resistor; Value: 0; Value_Code: 0000; Tolerance_%: 5; Power_W: 0.125; Value2: 0.125W; VDC_V: 150; TempCo: 600 ppm/C; SizeArea_mm2: 2.5; SizeX_mm: 2; SizeY_mm: 1.25; SizeZ_mm: 1.45; EIA_Code: E24; U/M: EA; AEC Category: Q200; Green_Lifecycle: Active; Green_REACh: Passed
R114 R115 = RC0603FR-0710KL: RES, 10.0 k, 1%, 0.1 W, 0603; Manufacturer: Yageo America; CompType: Resistor; Value: 10.0k; Res_ohm: 10000; Value_Code: 10k0; Tolerance_%: 1; Power_W: 0.1; Value2: 0.1W; VDC_V: 150; TempCo: 200 ppm/C; SizeArea_mm2: 1.28; SizeX_mm: 1.6; SizeY_mm: 0.8; EIA_Code: E96; U/M: EA; AEC Category: Q200; Green_Lifecycle: Active; Green_REACh: Passed
R116 = CRCW06031K00FKEA: RES, 1.00 k, 1%, 0.1 W, 0603; Manufacturer: Vishay-Dale; CompType: Resistor; Value: 1.00k; Res_ohm: 1000; Value_Code: 1k00; Tolerance_%: 1; Power_W: 0.1; Value2: 0.1W; VDC_V: 75; TempCo: 100 ppm/C; SizeArea_mm2: 1.28; SizeX_mm: 1.6; SizeY_mm: 0.8; EIA_Code: E96; U/M: EA; AEC Category: Q200; Green_Lifecycle: Active; Green_REACh: Passed
T1 = CMP-0030623-1: Transformer, 105uH, TH; Manufacturer: Wurth Elektronik; Green_Lifecycle: Active; DCR_ohm: 0.06; Green_REACh: Passed; Lp: 105; Ns1toNp: 1.1; Ind_H: 105µH
TP24 TP25 TP27 TP43 TP44 = 5000: Test Point, Miniature, Red, TH; Manufacturer: Keystone; CompType: Test Point Loop; ContactFinish: Silver
TP33 = 5002: Test Point, Miniature, White, TH; Manufacturer: Keystone; CompType: Test Point Loop; ContactFinish: Silver; Green_Lifecycle: Active; Green_REACh: Passed
U1 = LM5160DNTR: Wide Input 65V, 1.5A Synchronous Step-Down DC-DC Converter, DNT0012B; Alternate PartNumber: LM5160DNTT; Manufacturer: Texas Instruments; SymbolCreator: a0411947; CompType: IC; U/M: EA
U11 = CMP-0013424-7: 33-V Precision Surge Protection Clamp, DRV0006A (WSON-6); Manufacturer: Texas Instruments; Alternate PartNumber: TVS3300DRVT; SizeX_mm: 2; CompType: IC; SizeZ_mm: 0.8; SizeArea_mm2: 4; SizeAreaWB_mm2: 9; U/M: EA
U12 U14 U15 = CMP-0077837-1: 5-V Precision Surge Protection Clamp, DRV0006A (WSON-6); Alternate Manufacturer: Texas Instruments; SizeAreaWB_mm2: 9.0; SizeZ_mm: 0.8; SizeX_mm: 2.0; SizeArea_mm2: 4.0; CompType: IC; AEC Qualified: N; AEC Category: Q200
U13 = SN6505BDBVR: LOW-NOISE 1A TRANSFORMER DRIVERS FOR ISOLATED POWER SUPPLIES, DBV0006A; Alternate PartNumber: SN6505BDBVT; Manufacturer: Texas Instruments; SymbolCreator: Altium; SizeArea_mm2: 8.12; SizeAreaWB_mm2: 14.82; SizeX_mm: 2.8; SizeY_mm: 2.9; SizeZ_mm: 1.45; CompType: IC; U/M: EA
U24 = CMP-0067322-1: Overvoltage/Undervoltage Protection IC in SOT-23-5, DBV0005A (SOT-23-5); Alternate PartNumber: TPS2400DBVT; Alternate Manufacturer: Texas Instruments; Green_Lifecycle: Active; SizeAreaWB_mm2: 14.82; Green_REACh: Passed; U/M: EA; SizeZ_mm: 1.45; SizeX_mm: 2.8; SizeY_mm: 2.9; SizeArea_mm2: 8.12
U33 = CMP-0030760-1: Miniature, 1 W, 3 kVDC Isolated DC-DC Converter, -40 to 85 degC, 5-pin Module (EDJ5), Pb-Free (RoHS); Manufacturer: Texas Instruments; Vout(Min)(V): 14.25; Vin(Max)(V): 5.5; Iout(Max)(A): 0.033; Regulated Outputs(#): 2; Vin(Min)(V): 4.5; SubFamily: 1 W & 2 W Miniature; Vout(Max)(V): 15.75
U37 = CMP-0030757-1: Miniature, 1 W, 3 kVDC Isolated DC-DC Converter, -40 to 85 degC, 4-pin Module (EDJ4), Pb-Free (RoHS); Manufacturer: Texas Instruments; Regulated Outputs(#): 1; Vin(Max)(V): 5.5; Vin(Min)(V): 4.5; SubFamily: 1 W & 2 W Miniature; Iout(Max)(A): 0.2
U43 = CMP-0077265-1: 5.5-V, 2-A, 80 mohm Low Leakage Load Switch with RCB and Programmable Rise Time, DBV0006A (SOT-23-6); Alternate PartNumber: TPS22917DBVT; Alternate Manufacturer: Texas Instruments; SizeAreaWB_mm2: 14.82; SizeZ_mm: 1.45; SizeX_mm: 2.8; SizeY_mm: 2.9; SizeArea_mm2: 8.12; CompType: IC; AEC Qualified: N; AEC Category: Q200

## Sheet TIDA-00300_ISO_AFE-Power+Protection _Pg4.SchDoc: +/- 14V SPLIT RAIL
size 431 x 279 mm; Date: Not shown in title block; ApprovedBy: Not shown in title block; CheckedBy: Not shown in title block; Author: Not shown in title block; CompanyName: Not shown in title block; DrawnBy: Sreenivasa; Engineer: Not shown in title block; Organization: Not shown in title block; Address1: Not shown in title block; Address2: Not shown in title block; Address3: Not shown in title block; Address4: Not shown in title block; DocumentNumber: 1; Revision: Use project parameter SCH_Rev; SheetNumber: 4; SheetTotal: 6; PageSetup: Record=PageOptions¦CenterHorizontal=True¦CenterVertical=True¦PrintScale=0.62¦XCorrection=1.00¦YCorrection=1.00¦PrintKind=0¦BorderSize=5000000¦LeftOffset=0¦BottomOffset=0¦Orientation=2¦PaperLength=1000¦PaperWidth=1000¦Scale=100¦PaperSource=15¦PrintQuality=600¦MediaType=1¦DitherType=10¦PrintScaleMode=1¦PaperKind=Letter
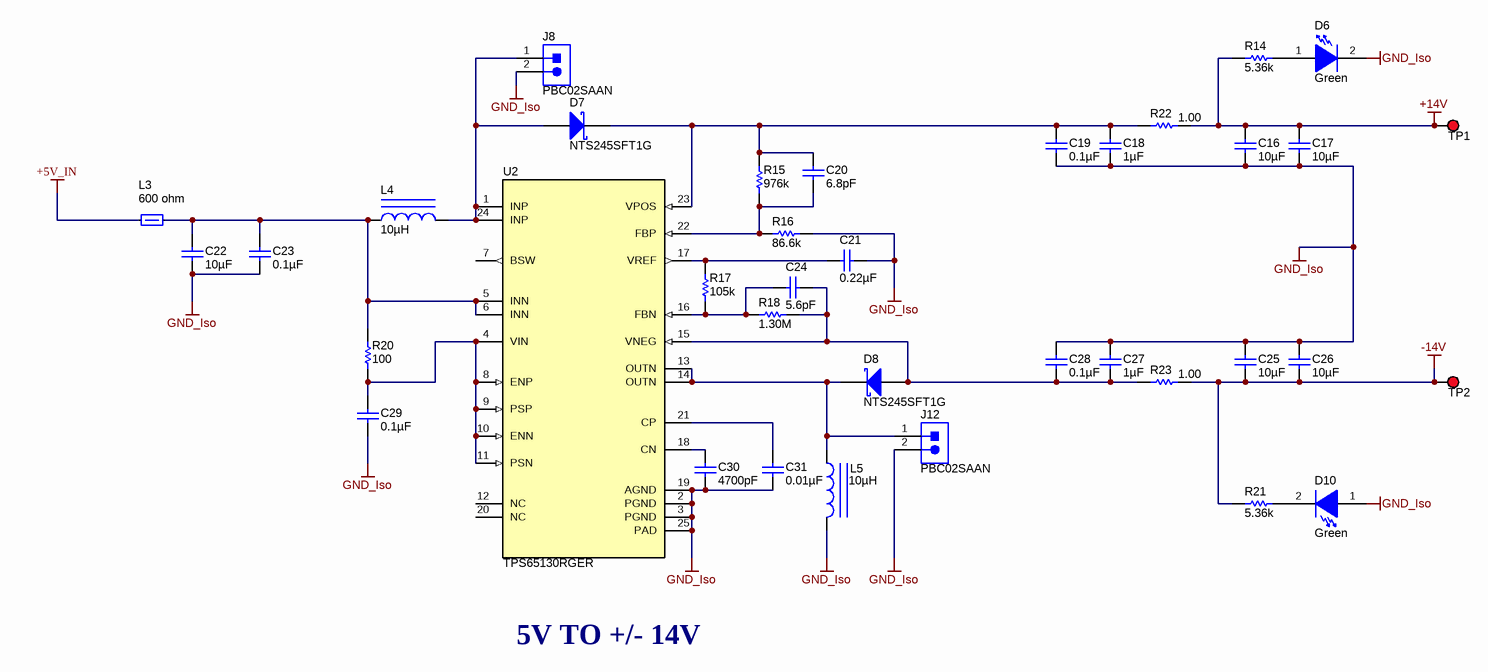
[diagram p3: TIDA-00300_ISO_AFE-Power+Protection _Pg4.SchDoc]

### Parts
C16  ValueDisplayed: 10µF  [0805_HV]  (hidden comment: GRM21BC71E106KE11L)
C17  ValueDisplayed: 10µF  [0805_HV]  (hidden comment: GRM21BC71E106KE11L)
C18  ValueDisplayed: 1µF  [0603S]  (hidden comment: CGA3E1X7R1E105K080AC)
C19  ValueDisplayed: 0.1µF  [0603S]  (hidden comment: C0603X124K5RAC7867)
C20  ValueDisplayed: 6.8pF  [0603S]  (hidden comment: 06035A6R8CAT2A)
C21  ValueDisplayed: 0.22µF  [0603S]  (hidden comment: GRM188R71C224KA01D)
C22  ValueDisplayed: 10µF  [0805_HV]  (hidden comment: GRM21BC71E106KE11L)
C23  ValueDisplayed: 0.1µF  [0603S]  (hidden comment: C0603X124K5RAC7867)
C24  ValueDisplayed: 5.6pF  [0603S]  (hidden comment: GRM1885C1H5R6DA01D)
C25  ValueDisplayed: 10µF  [0805_HV]  (hidden comment: GRM21BC71E106KE11L)
C26  ValueDisplayed: 10µF  [0805_HV]  (hidden comment: GRM21BC71E106KE11L)
C27  ValueDisplayed: 1µF  [0603S]  (hidden comment: CGA3E1X7R1E105K080AC)
C28  ValueDisplayed: 0.1µF  [0603S]  (hidden comment: C0603X124K5RAC7867)
C29  ValueDisplayed: 0.1µF  [0603S]  (hidden comment: C0603X124K5RAC7867)
C30  ValueDisplayed: 4700pF  [0603S]  (hidden comment: 885012206087)
C31  ValueDisplayed: 0.01µF  [0603S]  (hidden comment: 885012206040)
D6  value Green  [LED_LTST-C190_G]  (hidden comment: LTST-C190KGKT)
D7  NTS245SFT1G  [SOD-123FL]
D8  NTS245SFT1G  [SOD-123FL]
D10  value Green  [LED_LTST-C190_G]  (hidden comment: LTST-C190KGKT)
J8  PBC02SAAN  [Sullins_PBC02SAAN]
J12  PBC02SAAN  [Sullins_PBC02SAAN]
L3  value 600 ohm  [0603]  (hidden comment: BLM18KG601SN1D)
L4  ValueDisplayed: 10µH  [WE_LQS_252012]  (hidden comment: 74404024100)
L5  ValueDisplayed: 10µH  [WE_LQS_252012]  (hidden comment: 74404024100)
R14  ValueDisplayed: 5.36k  [0603S]  (hidden comment: CRCW06035K36FKEA)
R15  ValueDisplayed: 976k  [0603S]  (hidden comment: CRCW0603976KFKEA)
R16  ValueDisplayed: 86.6k  [0603S]  (hidden comment: CRCW060386K6FKEA)
R17  ValueDisplayed: 105k  [0603S]  (hidden comment: CRCW0603105KFKEA)
R18  ValueDisplayed: 1.30M  [0603S]  (hidden comment: CRCW06031M30FKEA)
R20  ValueDisplayed: 100  [0603S]  (hidden comment: CRCW0603100RFKEA)
R21  ValueDisplayed: 5.36k  [0603S]  (hidden comment: CRCW06035K36FKEA)
R22  ValueDisplayed: 1.00  [0603S]  (hidden comment: CRCW06031R00FKEA)
R23  ValueDisplayed: 1.00  [0603S]  (hidden comment: CRCW06031R00FKEA)
TP1  5000  [Keystone5000]  (value not drawn)
TP2  5000  [Keystone5000]  (value not drawn)
U2  TPS65130RGER  [RGE0024B]

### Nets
+5V_IN: L3.1
+14V: C16.1 C17.1 R14.1 R22.2 TP1.1
-14V: C25.2 C26.2 R21.2 R23.2 TP2.1
GND_Iso: C16.2 C17.2 C18.2 C19.2 C21.2 C22.2 C23.2 C25.1 C26.1 C27.1 C28.1 C29.2 C30.2 C31.2 D6.2(K) D10.1(A) J8.2 J12.2 L5.2 R16.1 U2.2(PGND) U2.3(PGND) U2.19(AGND) U2.25(PAD)
NetC18_1: C18.1 C19.1 C20.1 D7.1(K) R15.2 R22.1 U2.23(VPOS)
NetC20_2: C20.2 R15.1 R16.2 U2.22(FBP)
NetC21_1: C21.1 R17.2 U2.17(VREF)
NetC22_1: C22.1 C23.1 L3.2 L4.1 R20.2 U2.5(INN) U2.6(INN)
NetC24_1: C24.1 R17.1 R18.2 U2.16(FBN)
NetC24_2: C24.2 C27.2 C28.2 D8.2(A) R18.1 R23.1 U2.15(VNEG)
NetC29_1: C29.1 R20.1 U2.4(VIN) U2.8(ENP) U2.9(PSP) U2.10(ENN) U2.11(PSN)
NetC30_1: C30.1 U2.18(CN)
NetC31_1: C31.1 U2.21(CP)
NetD6_1: D6.1(A) R14.2
NetD7_2: D7.2(A) J8.1 L4.2 U2.1(INP) U2.24(INP)
NetD8_1: D8.1(K) J12.1 L5.1 U2.13(OUTN) U2.14(OUTN)
NetD10_2: D10.2(K) R21.1

Not connected (* = marked no-connect by the designer): U2 7(BSW) 12(NC) 20(NC)

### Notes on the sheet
- 5V TO +/- 14V

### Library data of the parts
C16 C17 C25 C26 = GRM21BC71E106KE11L: CAP, CERM, 10 µF, 25 V, +/- 10%, X7S, 0805; Manufacturer: MuRata; Polarized: N; CompType: Capacitor; Value: 10uF; U/M: EA; Cap_F: 0.00001; Tolerance_%: 10; Value1: Unknown; VDC_V: 25; Value2: 25V; TaMin_C: -55; TaMax_C: 125; Cap_Case: 0805; AEC Category: Q200
C18 C27 = GRM188R71E105KA12D: as C11 on sheet TIDA-00300_ISO_AFE-Power+Protection _Pg3
C19 C23 C28 C29 = C1608X7R1H104K: as C5 on sheet TIDA-00300_ISO_AFE-Power+Protection _Pg3
C20 = 06035A6R8CAT2A: CAP, CERM, 6.8 pF, 50 V, +/- 4%, C0G/NP0, 0603; Manufacturer: AVX; Polarized: N; CompType: Capacitor; Value: 6.8pF; U/M: EA; Cap_F: 0.0000000000068; Tolerance_%: 4; ESR_ohm: 0.505; Value1: 0.505 ohm; VDC_V: 50; Value2: 50V; TaMin_C: -55; TaMax_C: 125; Cap_Case: 0603; AEC Category: Q200
C21 = GRM188R71C224KA01D: CAP, CERM, 0.22 µF, 16 V, +/- 10%, X7R, 0603; Manufacturer: MuRata; Polarized: N; CompType: Capacitor; Value: 0.22uF; U/M: EA; Cap_F: 0.00000022; Tolerance_%: 10; Value1: Unknown; VDC_V: 16; Value2: 16V; TaMin_C: -55; TaMax_C: 125; Cap_Case: 0603; AEC Category: Q200
C22 = GRM21BC71E106KE11L: as C7 on sheet TIDA-00300_ISO_AFE-Power+Protection _Pg3
C24 = 06035A5R6CAT2A: CAP, CERM, 5.6 pF, 50 V, +/- 5%, C0G/NP0, 0603; Manufacturer: Murata; Polarized: N; CompType: Capacitor; Value: 5.6pF; U/M: EA; Cap_F: 0.0000000000056; Tolerance_%: 5; ESR_ohm: 0.568; Value1: 0.568 ohm; VDC_V: 50; Value2: 50V; TaMin_C: -55; TaMax_C: 125; Cap_Case: 0603; AEC Category: Q200
C30 = 885012206087: CAP, CERM, 4700 pF, 50 V, +/- 10%, X7R, 0603; Manufacturer: Wurth Elektronik; Polarized: N; CompType: Capacitor; Value: 4700pF; U/M: EA; Cap_F: 0.0000000047; Tolerance_%: 10; Value1: Unknown; VDC_V: 50; Value2: 50V; TaMin_C: -55; TaMax_C: 125; Cap_Case: 0603; AEC Category: Q200
C31 = 885012206040: CAP, CERM, 0.01 µF, 16 V, +/- 10%, X7R, 0603; Manufacturer: Wurth Elektronik; Polarized: N; CompType: Capacitor; Value: 0.01uF; U/M: EA; Cap_F: 0.00000001; Tolerance_%: 10; Value1: Unknown; VDC_V: 16; Value2: 16V; TaMin_C: -55; TaMax_C: 125; Cap_Case: 0603; AEC Category: Q200
D6 D10 = LTST-C190KGKT: as D1 on sheet TIDA-00300_ISO_AFE-Power+Protection _Pg3
D7 D8 = NTS245SFT1G: as D2 on sheet TIDA-00300_ISO_AFE-Power+Protection _Pg3
J8 J12 = PBC02SAAN: as J2 on sheet TIDA-00300_ISO_AFE-Power+Protection _Pg3
L3 = BLM18KG601SN1D: Ferrite Bead, 600 ohm @ 100 MHz, 1.3 A, 0603; Manufacturer: MuRata; Imax_A: 1.3; DCR_ohm: 0.15; Value1: 0.15 ohm; Value2: 1.3A; ZTyp@100MHz_Ohm: 600
L4 L5 = 74404024100: Inductor, Wirewound, Ferrite, 10 µH, 0.47 A, 0.435 ohm, SMD; Manufacturer: Wurth Elektronik; Value: 10uH; Ind_H: 10.0E-6; Imax_A: 0.47; Irms: 0.47A @ 40C rise; Isat: 0.85A @ 30% inductance drop; DCR_ohm: 0.435; Value2: 0.47A; AEC Category: Q200
R14 R21 = CRCW06035K36FKEA: as R8 on sheet TIDA-00300_ISO_AFE-Power+Protection _Pg3
R15 = CRCW0603976KFKEA: RES, 976 k, 1%, 0.1 W, 0603; Manufacturer: Vishay-Dale; CompType: Resistor; Value: 976k; Res_ohm: 976000; Tolerance_%: 1; Power_W: 0.1; Value2: 0.1W; VDC_V: 75; TempCo: 100 ppm/C; EIA_Code: E96; U/M: EA; AEC Category: Q200
R16 = CRCW060386K6FKEA: RES, 86.6 k, 1%, 0.1 W, 0603; Manufacturer: Vishay-Dale; CompType: Resistor; Value: 86.6k; Res_ohm: 86600; Value_Code: 86k6; Tolerance_%: 1; Power_W: 0.1; Value2: 0.1W; VDC_V: 75; TempCo: 100 ppm/C; EIA_Code: E96; U/M: EA; AEC Category: Q200
R17 = CRCW0603105KFKEA: RES, 105 k, 1%, 0.1 W, 0603; Manufacturer: Vishay-Dale; CompType: Resistor; Value: 105k; Res_ohm: 105000; Tolerance_%: 1; Power_W: 0.1; Value2: 0.1W; VDC_V: 75; TempCo: 100 ppm/C; EIA_Code: E96; U/M: EA; AEC Category: Q200
R18 = CRCW06031M30FKEA: RES, 1.30 M, 1%, 0.1 W, 0603; Manufacturer: Vishay-Dale; CompType: Resistor; Value: 1.30Meg; Res_ohm: 1300000; Value_Code: 1M30; Tolerance_%: 1; Power_W: 0.1; Value2: 0.1W; VDC_V: 75; TempCo: 100 ppm/C; EIA_Code: E96; U/M: EA; AEC Category: Q200
R20 = CRCW0603100RFKEA: RES, 100, 1%, 0.1 W, 0603; Manufacturer: Vishay-Dale; CompType: Resistor; Value: 100; Value_Code: 100R; Tolerance_%: 1; Power_W: 0.1; Value2: 0.1W; VDC_V: 75; TempCo: 100 ppm/C; EIA_Code: E96; U/M: EA; AEC Category: Q200
R22 R23 = CRCW06031R00FKEA: as R2 on sheet TIDA-00300_ISO_AFE-Power+Protection _Pg3
TP1 TP2 = 5000: as TP24 on sheet TIDA-00300_ISO_AFE-Power+Protection _Pg3
U2 = TPS65130RGER: Positive and Negative Output DC-DC Converter, RGE0024B; Alternate PartNumber: TPS65130RGET; Manufacturer: Texas Instruments; SymbolCreator: a0411947; CompType: IC; U/M: EA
